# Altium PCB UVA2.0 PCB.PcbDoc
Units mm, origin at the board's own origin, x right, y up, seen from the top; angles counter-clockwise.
Board outline 98.11 x 98.11 mm, 2 copper layers (Top Layer, Bottom Layer); 74 components, 54 nets, 233 pads, 126 vias.
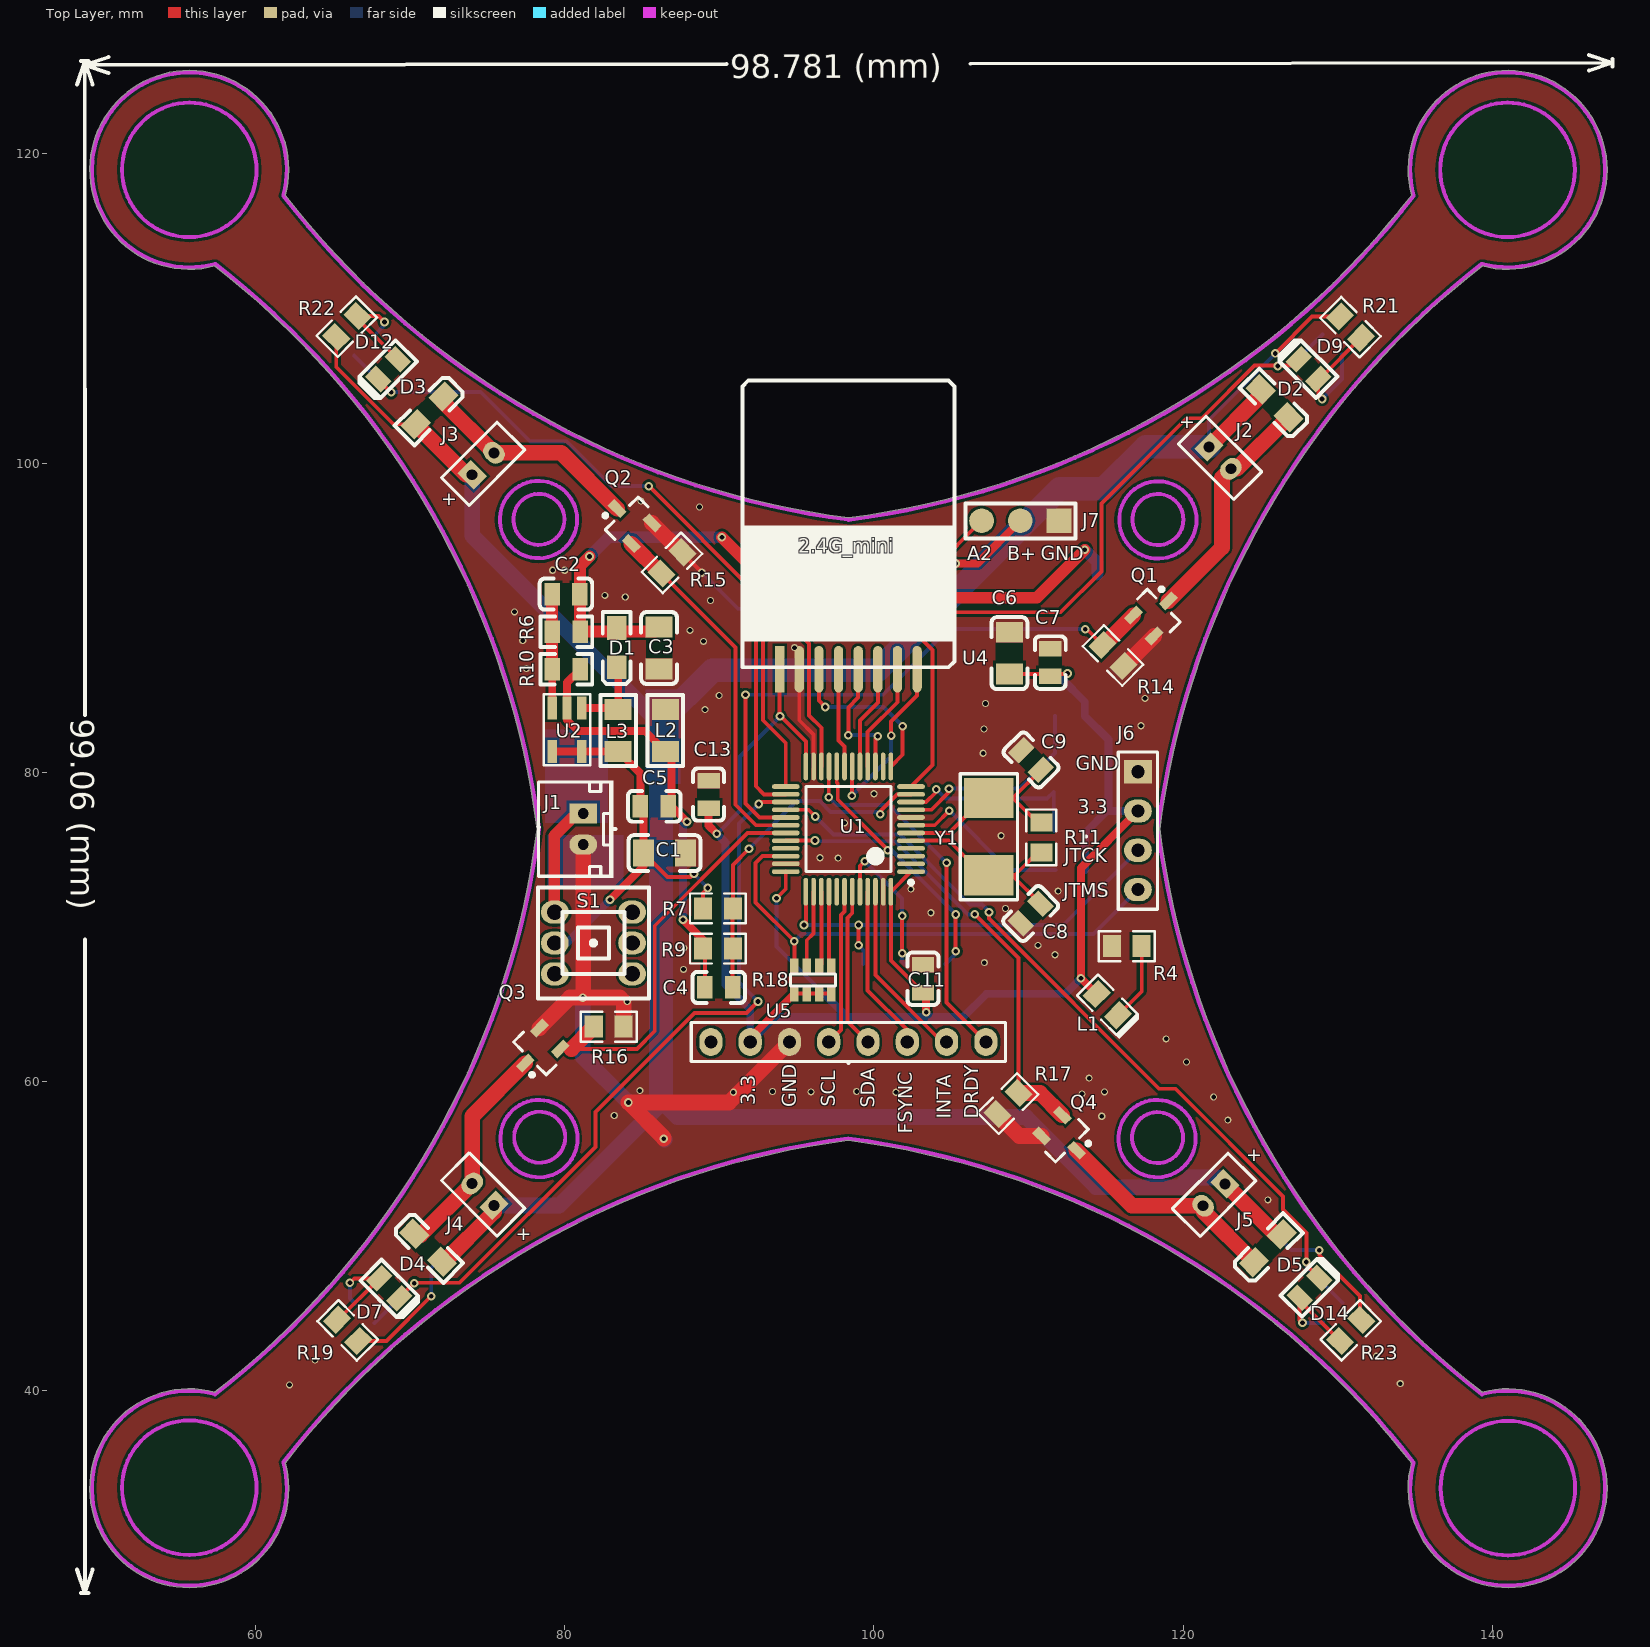
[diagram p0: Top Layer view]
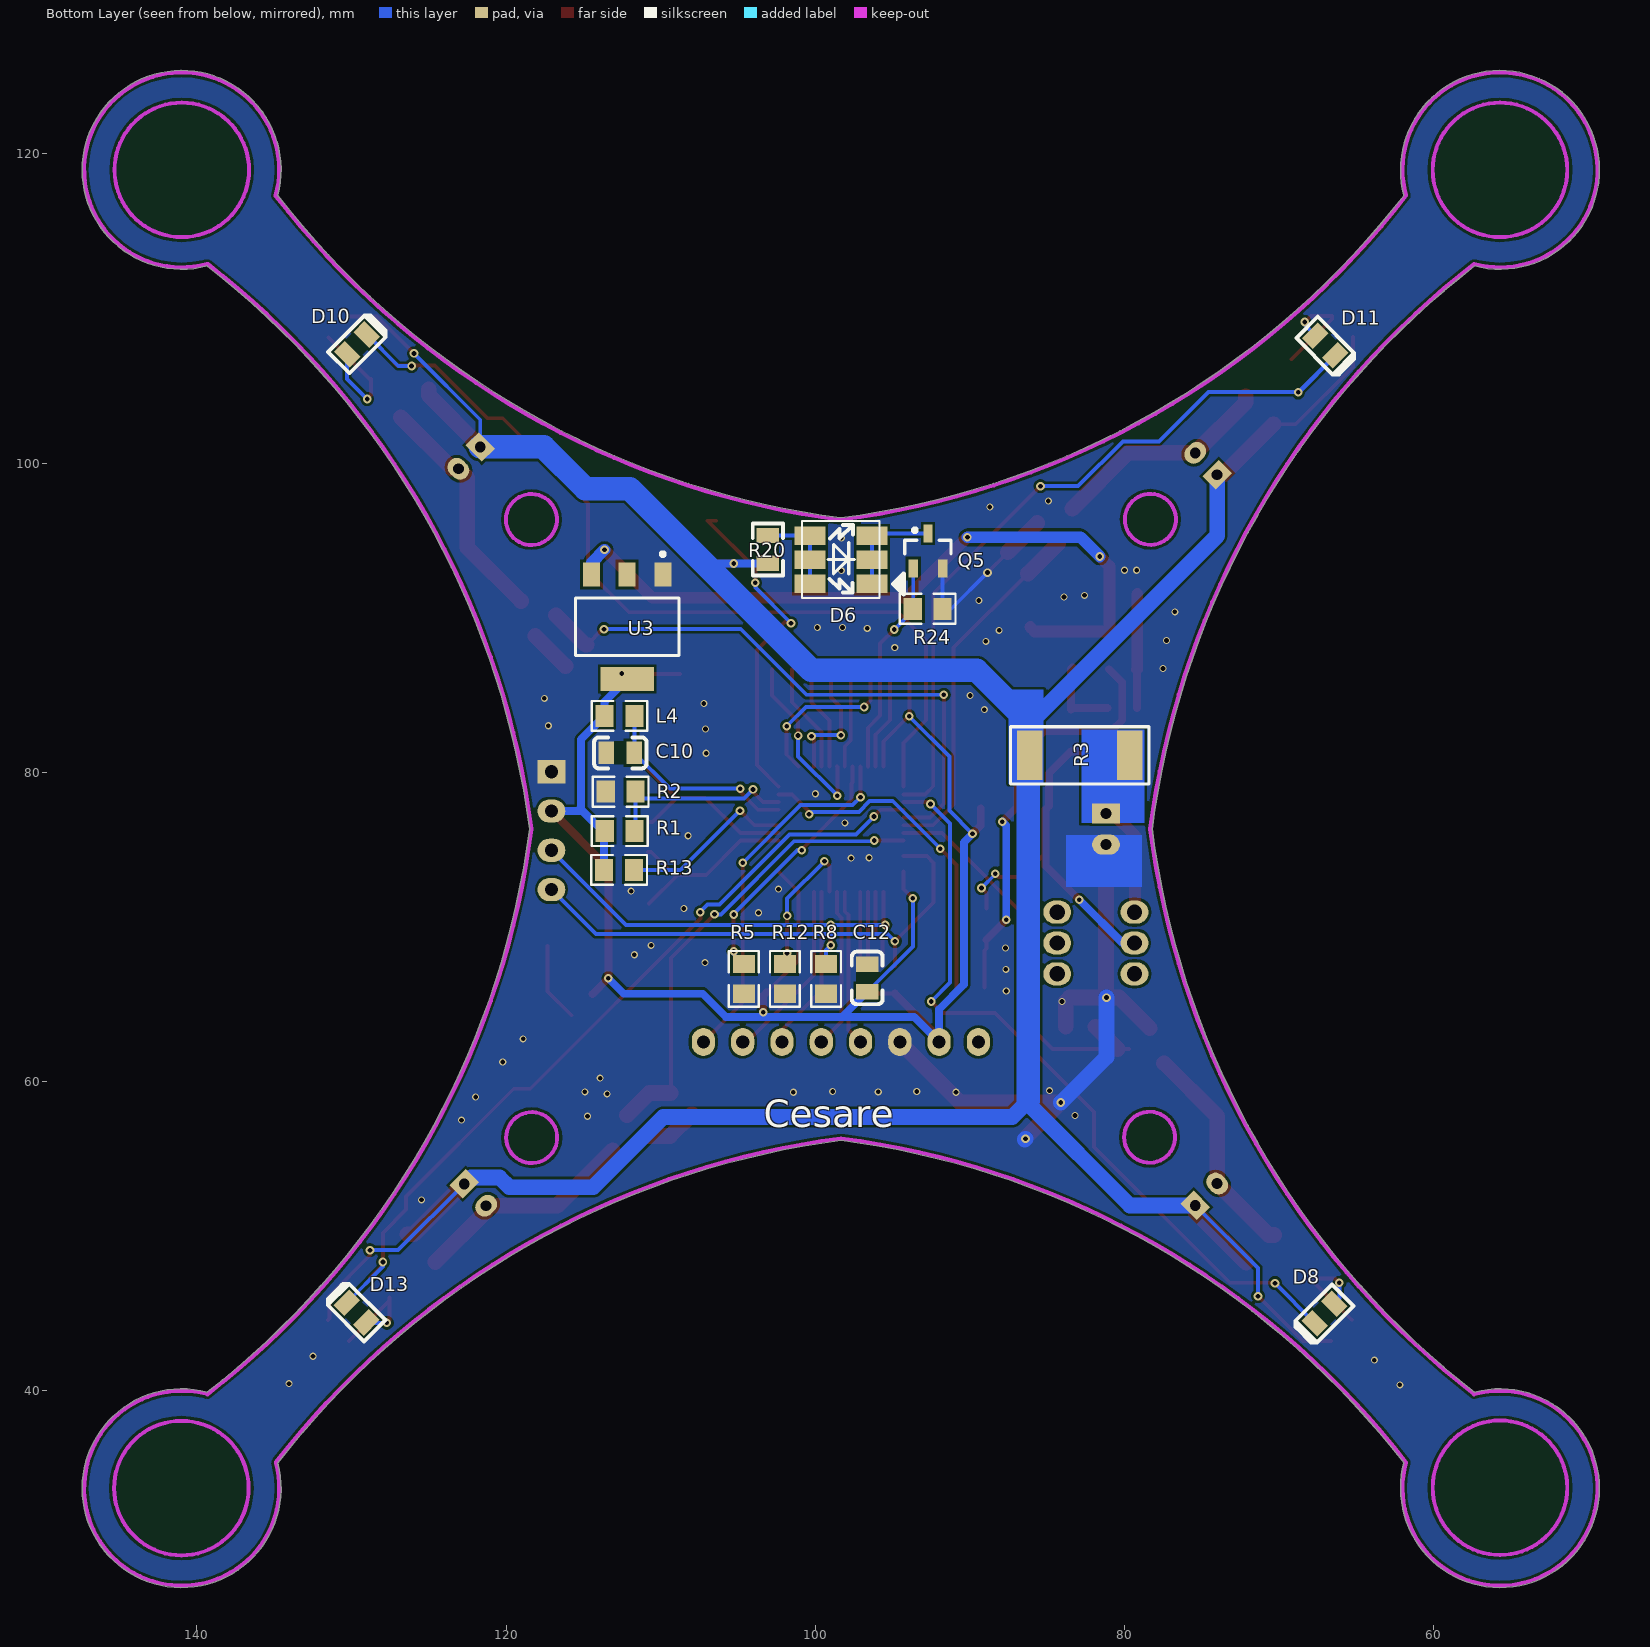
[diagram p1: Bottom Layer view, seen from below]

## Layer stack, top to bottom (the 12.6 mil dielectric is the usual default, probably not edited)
Top Solder: solder mask 0.0102, Solder Resist, Dk 3.5
Top Layer: signal copper 0.0356
Dielectric 1: dielectric 0.32, FR-4, Dk 4.8
Bottom Layer: signal copper 0.0356
Bottom Solder: solder mask 0.0102, Solder Resist, Dk 3.5

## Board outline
62.157,33.703 ccw(c55.73,33.703) 61.943,35.348 cw(c105.439,1.613) 98.338,56.198 cw(c91.255,1.611) 134.762,35.33 ccw(c140.981,33.703) 147.408,33.703 ccw(c140.981,33.703) 139.336,39.917 cw(c173.071,83.412) 118.484,76.329 cw(c173.071,69.245) 139.336,112.741 ccw(c140.981,118.954) 147.408,118.954 ccw(c140.981,118.954) 134.767,117.309 cw(c91.272,151.045) 98.355,96.457 cw(c105.439,151.045) 61.943,117.309 ccw(c55.73,118.954) 62.157,118.954 ccw(c55.73,118.954) 57.375,112.741 cw(c23.639,69.245) 78.226,76.329 cw(c23.639,83.412) 57.375,39.917 ccw(c55.73,33.703)

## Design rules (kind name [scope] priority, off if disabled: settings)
Clearance [All] p1: gap=0.178
PlaneConnect [All] p1: planeconnectstyle=Direct reliefexpansion=0.508 reliefentries=4 reliefconductorwidth=0.254 reliefairgap=0.254
PolygonConnect [All] p1: connectstyle=Direct reliefconductorwidth=0.254 reliefentries=4 polygonreliefangle="90 Angle" airgapwidth=0.254
RoutingVias [All] p1: holewidth=0.305 width=0.559 viastyle="Through Hole" minholewidth=0.305 minwidth=0.559 maxholewidth=0.711 maxwidth=1.27
SolderMaskExpansion [All] p1: expansion=0.102
Width [All] p1: maxlimit=1.524 minlimit=0.254 preferedwidth=0.254
28 further rules are at their usual default settings.

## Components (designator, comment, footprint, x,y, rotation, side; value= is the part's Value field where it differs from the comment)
C1 "10UF" 1206C 86.462,74.778 r180 top
C2 "3.3pF" 0805C 80.086,91.523 r180 top
C3 "4.7UF" 1206C 86.106,88.036 r270 top
C4 "100NF" 0805C 89.967,66.091 r180 top
C5 "4.7UF" 0805C 85.801,77.8 r0 top
C6 "10UF" 1206C 108.763,87.706 r90 top
C7 "0.1UF" 0805C 111.404,87.097 r90 top
C8 "20PF" 0805C 110.134,70.866 r45 top
C9 "20PF" 0805C 110.16,80.797 r315 top
C10 "100NF" 0805C 112.614,81.255 r0 bottom
C11 "100NF" 0805C 103.175,66.65 r90 top
C12 "100NF" 0805C 96.647,66.7 r90 bottom
C13 "100NF" 0805C 89.306,78.562 r90 top
D1 "DIODE-S" C_SMA_3216 83.363,88.062 r90 top
D2 "DIODE-S" C_SMA_3216 125.908,103.861 r135 top
D3 "DIODE-S" C_SMA_3216 71.272,103.403 r225 top
D4 "DIODE-S" C_SMA_3216 71.171,49.251 r315 top
D5 "DIODE-S" C_SMA_3216 125.476,49.225 r45 top
D6 "LED" LED5050_RGB 98.349,93.751 r180 bottom
D7 "LED" 0805D 68.656,46.634 r315 top
D8 "LED" 0805D 67.081,45.009 r315 bottom
D9 "LED" 0805D 128.097,106.07 r135 top
D10 "LED" 0805D 129.642,107.671 r135 bottom
D11 "LED" 0805D 67.031,107.594 r225 bottom
D12 "LED" 0805D 68.58,106.07 r225 top
D13 "LED" 0805D 129.667,45.06 r45 bottom
D14 "LED" 0805D 128.168,46.66 r45 top
J1 "Li Battery - 3.7V" P2_2.0-2 81.204,76.327 r270 top locked
J2 "M1" P2_2.0-1 122.377,100.33 r135 top
J3 "M1" P2_2.0-1 74.727,99.949 r225 top
J4 "M1" P2_2.0-1 74.727,52.7 r315 top
J5 "M1" P2_2.0-1 121.996,52.68 r45 top
J6 "ST_LINK" P4_2.54-1 117.069,76.225 r270 top
J7 "SIP3" PC_3 111.963,96.266 r180 top
L1 "白" D0805 114.427,65.634 r315 top
L2 "10UH" 1206 86.512,82.702 r270 top
L3 "10UH" 1206 83.464,82.702 r270 top
L4 "INDUCTOR" R0805 112.674,83.642 r180 bottom
Q1 "SI2302" SI2302 118.237,90.297 r45 top
Q2 "SI2302" SI2302 84.176,96.241 r135 top
Q3 "SI2302" SI2302 78.257,61.976 r225 top
Q4 "SI2302" SI2302 112.319,56.363 r315 top
Q5 "SI2302" SI2302 92.735,94.31 r90 bottom
R1 "RES" R0805 112.649,76.2 r0 bottom
R2 "RES" R0805 112.598,78.74 r180 bottom
R3 "0R" "2512R - duplicate" 82.906,81.102 r0 bottom
R4 "Res1" R0805 116.357,68.758 r180 top
R5 "RES" R0805 104.633,66.65 r270 bottom
R6 "620K" 0805R 80.108,89.083 r0 top
R7 "RES" R0805 89.907,71.196 r0 top
R8 "RES" R0805 99.314,66.65 r270 bottom
R9 "RES" R0805 89.918,68.604 r180 top
R10 "200K" 0805R 80.108,86.665 r180 top
R11 "RES" R0805 110.82,75.794 r270 top
R12 "RES" R0805 101.97,66.639 r90 bottom
R13 "RES" R0805 112.7,73.685 r180 bottom
R14 "RES" R0805 115.468,87.554 r135 top
R15 "RES" R0805 86.944,93.548 r225 top
R16 "RES" R0805 82.855,63.551 r180 top
R17 "RES" R0805 108.661,58.572 r45 top
R18 "10k" 8P4R_0603 96.037,66.573 r90 top
R19 "RES" R0805 65.964,43.917 r315 top
R20 "100R" 0805R 103.073,94.412 r90 bottom
R21 "RES" R0805 130.81,108.788 r315 top
R22 "RES" R0805 65.913,108.814 r45 top
R23 "RES" R0805 130.835,43.917 r225 top
R24 "RES" R0805 92.735,90.576 r0 bottom
S1 "SW-DPDT" KEY_KFT7.0 81.864,68.961 r180 top locked
U1 "STM32F103C8T6" LQFP48_N 98.349,76.327 r180 top locked
U2 "TPS6140" SOT-23-5 81.102,84.15 r270 top
U3 "AMS1117" ZZ311 112.166,89.408 r0 bottom
U4 "2.4G" 2.4G_mini 93.904,86.665 r0 top locked
U5 "GY_86" P8_2.54-1 98.349,62.56 r0 top locked
Y1 "CRYSTAL1" Y2 107.417,75.844 r270 top

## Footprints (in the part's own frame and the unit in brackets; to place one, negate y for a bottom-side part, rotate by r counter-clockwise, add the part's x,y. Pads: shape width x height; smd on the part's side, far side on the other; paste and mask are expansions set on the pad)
2.4G_mini [mm]
  rect 0.6x3 smd: 1(0,0)
  oval 0.6x3 smd: 2(1.27,0) 3(2.54,0) 4(3.81,0) 5(5.08,0) 6(6.35,0) 7(7.62,0) 8(8.89,0)
  silkscreen extent -2.41,0.13 11.3,18.67
8P4R_0603 [mil]
  rect 40x21.65 smd: 1(-35,46.5) 2(35,46.5) 3(-35,15) 4(35,15) 5(-35,-16.5) 6(35,-16.5) 7(-35,-47.99) 8(35,-47.99)
  silkscreen extent -15,-59 15,56
0805C [mm]
  rect 1x1.45 smd: 1(-0.9,0) 2(0.9,0)
  Top Layer pour cut-out: -0.432,0.749 -0.432,-0.737 0.406,-0.737 0.406,0.749
  silkscreen extent -1.7,-1 1.7,1, body extent -1,-0.61 1,0.64, height 1
0805D [mm]
  rect 1x1.45 smd: 1(-0.9,0) 2(0.9,0)
  Top Layer pour cut-out: -0.432,0.749 -0.432,-0.737 0.406,-0.737 0.406,0.749
  silkscreen extent -1.66,-0.98 1.94,0.98, body extent -1.16,-0.68 1.14,0.67, height 0.76
0805R [mm]
  rect 1x1.45 smd: 1(-0.9,0) 2(0.9,0)
  Top Layer pour cut-out: -0.432,0.749 -0.432,-0.737 0.406,-0.737 0.406,0.749
  silkscreen extent -1.68,-0.98 1.68,0.98, body extent -1,-0.62 1,0.63, height 0.5
1206 [mm]
  rect 1.35x1.75 smd: 1(-1.35,0) 2(1.35,0)
  Top Layer pour cut-out: -0.686,0.864 0.673,0.864 0.673,-0.876 -0.686,-0.876
  silkscreen extent -2.3,-1.14 2.3,1.14, body extent -1.61,-0.81 1.59,0.79, height 1.5
1206C [mm]
  rect 1.35x1.75 smd: 1(-1.35,0) 2(1.35,0)
  Top Layer pour cut-out: -0.686,0.876 0.673,0.876 0.673,-0.864 -0.686,-0.864
  silkscreen extent -2.32,-1.16 2.32,1.16, body extent -1.65,-0.81 1.55,0.79, height 1
"2512R - duplicate" [mm]
  rect 1.65x3.2 smd: 1(-3.24,0) 2(3.24,0)
  silkscreen extent -4.49,-1.84 4.48,1.87, body extent -2.48,-1.26 2.52,1.24, height 0.6
C_SMA_3216 [mil] "英制1206/公制3216"
  rect 60x50 smd: 1(-50,0) 2(50,0)
  Top Layer pour cut-out: -19.68,29.53 19.68,29.53 19.68,-29.53 -19.68,-29.53
  silkscreen extent -93,-35 91,35, body extent -66,-33 68,33, height 67
D0805 [mil]
  rect 46x56 smd: 1(-1,0) 2(75,0)
  silkscreen extent -34,-40 120,40
KEY_KFT7.0 [mm] "7X7mm"
  oval 1.8x1.5 hole 1: 1(-2.5,2) 2(-2.5,0) 3(-2.5,-2) 4(2.5,-2) 5(2.5,0) 6(2.5,2)
  silkscreen extent -3.6,-3.6 3.6,3.6
LED5050_RGB [mm]
  rect 2x1.2 smd paste-0.05 mask+0.05: 1(-2,1.55) 2(-2,0) 3(-2,-1.55) 4(2,-1.55) 5(2,0) 6(2,1.55)
  silkscreen extent -2.51,-2.49 4.06,2.51, body extent -2.68,-2.5 2.62,2.5, height 1.6
LQFP48_N [mm]
  oval 1.8x0.3 smd: 1(-4.05,2.75) 2(-4.05,2.25) 3(-4.05,1.75) 4(-4.05,1.25) 5(-4.05,0.75) 6(-4.05,0.25) 7(-4.05,-0.25) 8(-4.05,-0.75) 9(-4.05,-1.25) 10(-4.05,-1.75) 11(-4.05,-2.25) 12(-4.05,-2.75) 25(4.05,-2.75) 26(4.05,-2.25) 27(4.05,-1.75) 28(4.05,-1.25) 29(4.05,-0.75) 30(4.05,-0.25) 31(4.05,0.25) 32(4.05,0.75) 33(4.05,1.25) 34(4.05,1.75) 35(4.05,2.25) 36(4.05,2.75)
  oval 0.3x1.8 smd: 13(-2.75,-4.05) 14(-2.25,-4.05) 15(-1.75,-4.05) 16(-1.25,-4.05) 17(-0.75,-4.05) 18(-0.25,-4.05) 19(0.25,-4.05) 20(0.75,-4.05) 21(1.25,-4.05) 22(1.75,-4.05) 23(2.25,-4.05) 24(2.75,-4.05) 37(2.75,4.05) 38(2.25,4.05) 39(1.75,4.05) 40(1.25,4.05) 41(0.75,4.05) 42(0.25,4.05) 43(-0.25,4.05) 44(-0.75,4.05) 45(-1.25,4.05) 46(-1.75,4.05) 47(-2.25,4.05) 48(-2.75,4.05)
  silkscreen extent -4.18,-2.75 2.75,3.57
P2_2.0-1 [mm]
  rect 1.2x1.5 hole 0.7: 1(1,0)
  oval 1.2x1.5 hole 0.7: 2(-1,0)
  silkscreen extent -2.54,-1.27 2.54,1.27
P2_2.0-2 [mm]
  rect 1.3x1.8 hole 0.7: 1(-1,0)
  oval 1.3x1.8 hole 0.7: 2(1,0)
  silkscreen extent -3.15,-2.9 3.16,1.97, body extent -2.99,-2.8 3.01,1.7, height 6
P4_2.54-1 [mm]
  rect 1.5x1.8 hole 0.85: 1(-3.81,0)
  oval 1.5x1.8 hole 0.85: 2(-1.27,0) 3(1.27,0) 4(3.81,0)
  silkscreen extent -5.08,-1.27 5.08,1.27, body extent -5.08,-1.47 5.08,1.45, height 8.56
P8_2.54-1 [mm]
  oval 1.5x1.8 hole 0.85: 1(-8.89,0) 2(-6.35,0) 3(-3.81,0) 4(-1.27,0) 5(1.27,0) 6(3.81,0) 7(6.35,0) 8(8.89,0)
  silkscreen extent -10.16,-1.27 10.16,1.27, body extent -10.16,-1.47 10.16,1.45, height 8.56
PC_3 [mm]
  rect 1.6x1.6 smd: 1(0,0)
  round 1.6 smd: 2(2.5,0) 3(5,0)
  silkscreen extent -1.07,-1.12 6.05,1.14
R0805 [mil]
  rect 46x56 smd: 1(-37.79,0.07) 2(38.21,0.07)
  silkscreen extent -71,-38 71,38
SI2302 [mm]
  rect 1.15x0.6 smd: 1(-1.128,0.934) 2(-1.128,-0.966) 3(1.122,-0.016)
  silkscreen extent -0.2,-1.52 1.47,1.48, body extent -0.7,-1.52 0.7,1.48, height 1.1
SOT-23-5 [mm]
  rect 1.5x0.6 smd: 1(0,0) 2(0,-0.95) 3(0,-1.9) 4(2.8,-1.9) 5(2.8,0)
  silkscreen extent -0.9,-2.45 3.7,0.55
Y2 [mm]
  rect 2.6x3.2 smd: 1(-2.5,0) 2(2.5,0)
  silkscreen extent -4.06,-1.83 4.09,1.87
ZZ311 [mm]
  rect 1.1x1.55 smd: 1(-2.3,-3.375) 2(0,-3.375) 3(2.3,-3.375)
  rect 3.45x1.55 smd: 4(0,3.375)
  silkscreen extent -3.35,-4.82 3.35,1.85

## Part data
C1 C2 C3 C4 C5 C6 C7 C8 C9 C10 C11 C12 C13: library part CAP, "Capacitor/小容量电容"
D1 D2 D3 D4 D5: "SCHOTTKEY"
D6: library part LED_5050RGB
J1 J2 J3 J4 J5: library part SIP2
J6: library part SIP4
L1: library part LED
L2 L3: library part L
R1 R2 R5 R7 R8 R9 R11 R12 R13 R14 R15 R16 R17 R19 R21 R22 R23 R24: "Semiconductor Resistor"
R3: library part Res_1
R4: "Resistor"
R6 R10 R20: library part Res
R18: library part 8P4R_0603, "8P4R_0603"
S1: "Double-Pole, Double-Throw Switch"
U1: "STM32 ARM-based 32-bit MCU with 64 Kbytes Flash, 48-pin LQFP, Industrial Temperature"
U3: "Header, 2-Pin"
U4: library part 2.4G_mini

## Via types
v1: diameter 0.559, hole 0.305, Top Layer to Bottom Layer, 65 vias
v2: diameter 0.457, hole 0.305, Top Layer to Bottom Layer, 61 vias

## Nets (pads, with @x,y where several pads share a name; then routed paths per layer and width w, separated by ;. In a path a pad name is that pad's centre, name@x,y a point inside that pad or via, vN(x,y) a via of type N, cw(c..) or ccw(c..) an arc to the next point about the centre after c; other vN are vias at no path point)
2.4_CE: U1.13 U4.3 | length 11
  Top Layer w0.254: U4.3 96.444,84.633 v1(96.85,84.226) ; U1.13 101.854,81.132 v1(101.854,82.982)
  Bottom Layer w0.254: v1(96.85,84.226) 100.609,84.226 v1(101.854,82.982)
2.4_CSN: U1.19 U4.4 | length 6.4
  Top Layer w0.254: U4.4 97.714,82.042 98.099,81.657 U1.19
2.4_IRQ: U1.18 U4.8 | length 11.8
  Top Layer w0.254: v1(98.577,78.486) 98.577,80.356 U1.18 ; v1(101.117,82.372) 101.117,83.287 102.794,84.963 U4.8
  Bottom Layer w0.254: v1(98.577,78.486) 101.117,81.026 v1(101.117,82.372)
2.4_MISO: U1.16 U4.7 | length 7.1
  Top Layer w0.254: U1.16 99.599,82.606 101.524,84.531 U4.7
2.4_MOSI: U1.17 U4.6 | length 6.8
  Top Layer w0.254: U1.17 99.099,83.351 100.254,84.506 U4.6
2.4_SCK: U1.15 U4.5 | length 8.5
  Top Layer w0.254: v1(98.349,82.398) 98.349,84.201 98.984,84.836 U4.5 ; U1.15 100.099,82.166 v1(100.254,82.321)
  Bottom Layer w0.254: v1(98.349,82.398) 100.178,82.398 v1(100.254,82.321)
505LED: Q5.1 R24.2 U1.22 | length 14
  Top Layer w0.254: v1(94.894,89.23) 95.809,88.316 95.809,83.668 96.599,82.878 U1.22
  Bottom Layer w0.254: Q5.1 93.669,90.455 v1(94.894,89.23)
+3.3V: C6.1 C7.1 C11.1 C12.1 C13.1 J6.2 L1.1 L4.1 R1.2 R13.1 R18.1 R18.3 R18.5 R18.7 U1.1 U1.24 U1.36 U1.48 U3.4 U4.1 U5.2 | length 119.1
  Top Layer w0.254: v1(93.701,71.857) 94.299,72.455 U1.36 ; U4.1 93.904,83.693 v1@93.929,83.668 ; v1(93.929,83.617) v1@93.929,83.668 ; R18.1 R18.3 R18.5 R18.7 ; U1.24 95.599,81.998 v1@93.929,83.668 ; U1.1 U1.48 101.099,67.826 C11.1 ; C6.1 112.49,86.356 v1(112.519,86.385)
  Top Layer w0.508: C13.1 89.306,76.556 v1(89.84,76.022) ; U5.2 91.999,62.827 R18.1 ; C11.1 103.378,65.546 v1(103.378,64.491) ; L1.1 v1(113.386,66.675) 113.386,73.812 J6.2
  Bottom Layer w0.254: v1(89.84,76.022) 91.338,77.521 91.338,81.026 v1(93.929,83.617) ; v1(93.701,71.857) 93.701,68.747 C12.1 ; U3.4 v1(112.519,86.385)
  Bottom Layer w0.508: v1(89.84,76.022) 90.399,75.463 90.399,66.279 91.999,64.679 U5.2 93.624,64.186 98.262,64.186 ; C12.1 98.262,64.186 ; 103.378,64.186 98.262,64.186 ; v1(103.378,64.491) 103.403,64.465 103.403,64.186 105.798,64.186 107.291,65.679 112.39,65.679 v1(113.386,66.675) ; U3.4 113.634,84.565 L4.1 115.164,82.115 115.164,77.699 115.367,77.495 ; R13.1 113.66,76.093 115.062,77.495 J6.2
+5.0V: C2.1 C3.1 D1.2 R6.2 U3.3 | length 47.7
  Top Layer w0.762: v1(81.61,93.955) 80.986,93.331 C2.1 80.986,89.104 85.824,89.104 C3.1 ; v1(90.17,95.199) 94.082,91.288 110.541,91.288 v1(113.64,94.386)
  Bottom Layer w0.762: v1(81.61,93.955) 82.855,95.199 v1(90.17,95.199) ; v1(113.64,94.386) 114.466,93.56 U3.3
ADC: C4.1 R7.2 R9.1 U1.11 | length 22.1
  Top Layer w0.254: C4.1 90.867,71.187 R7.2 90.877,74.012 v1(91.923,75.057) ; v1(100.406,77.292) 100.406,77.478 101.506,78.577 U1.11
  Bottom Layer w0.254: v1(91.923,75.057) 94.996,78.13 96.507,78.13 97.192,77.445 100.254,77.445 v1(100.406,77.292)
BAT: J1.1 R3.1 S1.4 | length 7.4
  Top Layer w0.762: S1.4@79.35,70.942 79.324,70.968 79.324,75.895 80.756,77.327 J1.1
BAT+: D2.2 D3.2 D4.2 D5.2 J2.1 J3.1 J4.1 J5.1 J7.2 R3.2 R19.2 R20.1 R21.1 R22.1 R23.1 | length 216.8
  Top Layer w0.254: R22.1 65.233,106.217 68.945,102.505 D3.2 ; R19.2 68.479,43.232 v1(71.374,46.126) ; v1(125.959,107.086) 128.34,109.468 R21.1 ; v1(128.803,49.098) 128.803,48.768 131.432,46.139 131.432,44.677 R23.1
  Top Layer w0.508: v1(105.283,93.497) 106.695,93.497 J7.2
  Top Layer w1.016: D3.2 73.638,99.242 J3.1 ; D4.2@72.145,48.276 75.434,51.565 J4.1 ; J2.1 125.01,104.377 D2.2 ; J5.1 125.967,50.123 D5.2
  Bottom Layer w0.254: v1(71.374,46.126) 71.374,47.933 J4.1 ; J2.1 121.67,102.798 v1(125.959,107.086) ; J5.1 126.992,49.098 v1(128.803,49.098)
  Bottom Layer w0.508: R20.1 v1@105.283,93.512 ; v1(105.283,93.497) 106.858,93.497 107.01,93.345
  Bottom Layer w1.016: J3.1 74.02,95.297 86.144,83.172 ; J4.1 79.654,51.993 86.233,58.572 ; 86.233,58.75 87.274,57.709 109.83,57.709 114.364,53.175 119.799,53.175 120.421,53.797 122.293,53.797 J5.1
  Bottom Layer w1.524: 86.144,83.172 89.56,86.589 100.254,86.589 107.01,93.345 112.014,98.349 114.884,98.349 117.573,101.037 J2.1 ; 86.233,58.75 86.233,80.05 R3.2@86.716,80.532
GND: C1.1 C3.2 C6.2 C7.2 C8.1 C9.1 C10.2 C11.2 C12.2 C13.2 J1.2 J6.1 J7.1 L2.1 Q1.2 Q2.2 Q3.2 Q4.2 Q5.2 R2.1 R4.2 R5.2 R8.2 R12.1 R14.1 R15.1 R16.1 R17.1 R24.1 U1.8 U1.23 U1.35 U1.47 U3.1 U4.2 U5.3 | length 65.2
  Top Layer w0.254: R15.1@87.557,94.226 87.562,94.226 v1(88.875,92.913) ; U4.2 95.174,83.363 96.099,82.438 U1.23
  Top Layer w1.016: Q3.2 80.346,65.43 v1(81.178,65.43) ; J1.2 81.204,65.456 v1(81.178,65.43) ; R16.1 83.815,65.182 83.566,65.43 v1(81.178,65.43) ; Q2.2 R15.1@87.557,94.226 ; v1(86.411,56.312) 86.411,56.363 v1(84.125,58.649) 90.627,58.649 U5.3 ; R17.1 109.399,56.477 Q4.2 ; R14.1 116.18,86.874 Q1.2
  Bottom Layer w0.254: v1(88.875,92.913) 91.213,90.575 R24.1 91.769,90.581 Q5.2
  Bottom Layer w1.016: v1(81.178,65.43) 81.178,61.595 v1(84.125,58.649) ; v1(86.411,56.312) v1@86.462,56.261
  other v2: 62.205,40.386 134.036,40.462 63.856,41.986 132.486,42.24 125.476,52.349 122.885,57.506 114.732,57.76 83.21,57.81 121.971,59.004 113.462,59.207 90.907,59.309 101.422,59.309 95.936,59.334 114.91,59.334 93.447,59.36 98.882,59.36 84.861,59.411 113.919,60.223 120.218,61.265 118.897,62.763 84.049,65.176 87.655,65.862 87.681,67.259 107.137,67.691 111.709,68.199 87.706,68.631 110.617,68.809 103.683,70.917 108.509,71.196 111.912,72.314 102.387,72.441 97.688,74.447 96.52,74.473 108.229,75.895 98.095,76.733 100,78.613 107.061,81.229 107.112,82.804 117.272,83.007 89.078,84.049 107.213,84.455 117.526,84.785 89.992,84.963 77.521,86.716 94.869,88.062 88.976,88.468 77.292,88.519 88.113,89.179 96.647,89.306 98.247,89.357 99.873,89.357 76.759,90.373 89.433,91.11 83.922,91.338 82.601,91.44 98.323,93.04 79.223,93.066 80.01,93.066 98.323,95.148 88.722,97.155 84.938,97.536
GY_DRDY: U1.21 U5.8 | length 24
  Top Layer w0.254: v1(97.079,78.384) 97.079,80.357 U1.21 ; v1(104.699,74.143) 104.699,65.1 U5.8
  Bottom Layer w0.254: v1(97.079,78.384) 97.587,77.876 100.965,77.876 v1(104.699,74.143)
GY_FSYNC: U1.45 U5.6 | length 10.8
  Top Layer w0.254: U1.45 99.599,65.882 102.159,63.322 U5.6
GY_INTA: U1.46 U5.7 | length 11.8
  Top Layer w0.254: U1.46 100.099,66.881 104.419,62.56 U5.7
GY_SCL: U1.42 U5.4 | length 10.1
  Top Layer w0.254: U5.4 97.866,63.348 97.866,70.765 98.099,70.998 U1.42
GY_SDA: U1.43 U5.5 | length 10.4
  Top Layer w0.254: U1.43 98.599,70.887 98.298,70.587 98.298,63.881 U5.5
JTCK: J6.3 R8.1 U1.37 | length 28.4
  Top Layer w0.254: v1(95.479,70.129) 95.599,70.25 U1.37 ; v1(99.009,68.809) v1(99.009,70.129)
  Bottom Layer w0.254: v1(95.479,70.129) v1(99.009,70.129) 112.243,70.129 J6.3 ; v1(99.009,68.809) 99.312,68.506 R8.1
JTDI: R18.4 U1.38 | length 5
  Top Layer w0.254: R18.4 95.656,69.139 96.099,69.581 U1.38
JTDO: R18.6 U1.39 | length 4.9
  Top Layer w0.254: R18.6 96.599,67.605 U1.39
JTMS: J6.4 R18.2 U1.34 | length 33.4
  Top Layer w0.254: U1.34 92.789,74.577 92.354,74.143 92.354,71.577 v1(94.856,69.075) R18.2
  Bottom Layer w0.254: v1(94.856,69.075) 95.326,69.545 114.198,69.545 J6.4
JTRST: R18.8 U1.40 | length 4.9
  Top Layer w0.254: U1.40 97.099,67.62 R18.8
LED_1: D9.2 D10.2 U1.25 | length 58.5
  Top Layer w0.254: U1.25 94.299,81.901 92.837,83.363 92.837,88.519 94.666,90.348 112.065,90.348 114.706,92.989 114.706,97.384 120.218,102.895 121.209,102.895 124.612,106.299 127.053,106.299 D9.2
  Bottom Layer w0.254: v1(126.111,106.274) 126.972,106.274 D10.2
LED_2: D11.2 D12.2 U1.26 | length 51.6
  Top Layer w0.254: D12.2 67.944,105.409 v1(68.783,104.569) ; v1(85.446,98.501) 92.38,91.567 92.38,79.096 92.898,78.577 U1.26
  Bottom Layer w0.254: v1(68.783,104.569) D11.2 66.394,106.91 68.707,104.597 74.574,104.597 77.775,101.397 80.112,101.397 83.007,98.501 v1(85.446,98.501)
LED_3: D7.2 D8.2 U1.27 | length 51.7
  Top Layer w0.254: D7.2 v1@70.27,46.976 ; v1@70.285,46.99 73.198,46.99 81.991,55.783 81.991,58.039 88.392,64.44 91.77,64.44 v1(92.507,65.176) ; v1(92.558,77.953) 92.682,78.077 U1.27
  Bottom Layer w0.254: D8.2 67.718,44.401 v1(70.282,46.965) ; v1(92.507,65.176) 91.288,66.396 91.288,76.683 v1(92.558,77.953)
LED_4: D13.2 D14.2 U1.28 | length 52.6
  Top Layer w0.254: U1.28 95.778,77.577 v1(96.215,77.14) ; v1(107.442,70.942) 107.442,70.536 118.44,59.538 119.507,59.538 126.467,52.578 126.467,51.714 127.965,50.216 v1(127.965,48.336) 127.965,48.136 D14.2
  Bottom Layer w0.254: v1(96.215,77.14) 97.384,75.971 101.676,75.971 106.197,71.45 106.985,71.45 107.442,70.993 v1(107.442,70.942) ; v1(127.965,48.336) 127.965,48.034 D13.2
MOS_1: Q1.1 R14.2 U1.29 | length 38.1
  Top Layer w0.254: v1(91.694,85.014) 91.694,77.978 92.595,77.077 U1.29 ; v1(113.665,89.256) 113.764,89.256 R14.2
  Top Layer w1.016: R14.2 114.858,88.239 Q1.1
  Bottom Layer w0.254: v1(91.694,85.014) 100.584,85.014 104.826,89.256 v1(113.665,89.256)
MOS_2: Q2.1 R15.2 U1.30 | length 23.5
  Top Layer w0.254: R15.2 91.059,88.061 91.059,77.902 92.384,76.577 U1.30
  Top Layer w1.016: Q2.1 86.235,92.861 R15.2
MOS_3: Q3.1 R16.2 U1.31 | length 26.4
  Top Layer w0.254: Q3.1 80.448,62.113 84.668,62.113 85.827,63.271 85.827,70.079 91.825,76.077 U1.31
  Top Layer w1.016: 80.448,62.113 R16.2
MOS_4: Q4.1 R17.2 U1.32 | length 30.4
  Top Layer w0.254: U1.32 96.176,75.577 v1(96.19,75.59) ; v1(106.528,70.815) 109.346,67.997 R17.2
  Top Layer w1.016: R17.2 110.742,59.26 Q4.1
  Bottom Layer w0.254: v1(96.19,75.59) 96.241,75.54 101.371,75.54 106.096,70.815 v1(106.528,70.815)
NetC1_2: C1.2 C5.1 L3.2 R7.1 S1.5 U2.4 U2.5 | length 26.9
  Top Layer w0.254: C1.2 86.66,73.229 88.151,73.229 v1(88.367,73.445) ; R7.1 88.947,72.208 v1(89.256,72.517)
  Top Layer w0.508: U2.4 U2.5 83.462,81.35 L3.2 84.901,79.916 C5.1 85.112,77.59 C1.2 85.112,73.936 v1(82.931,71.755)
  Bottom Layer w0.254: v1(88.367,73.445) 88.367,73.406 v1(89.256,72.517)
  Bottom Layer w0.508: S1.5 80.137,68.961 v1(82.931,71.755)
NetC2_2: C2.2 R6.1 R10.2 U2.3 | length 7.4
  Top Layer w0.508: U2.3 79.202,86.659 R10.2
  Top Layer w0.762: C2.2 79.186,86.686 R10.2
NetC8_2: C8.2 R11.2 U1.5 Y1.2 | length 12.6
  Top Layer w0.254: U1.5 104.839,75.577 107.072,73.344 Y1.2 109.108,73.344 110.612,74.848 R11.2@110.822,74.848 ; Y1.2@108.929,73.344 C8.2
NetC9_2: C9.2 R11.1 U1.6 Y1.1 | length 12.6
  Top Layer w0.254: U1.6 104.855,76.077 107.123,78.344 Y1.1 Y1.1@108.98,78.344 ; C9.2 Y1.1@108.98,78.344 ; R11.1@110.822,76.779 110.545,76.779 Y1.1@108.98,78.344
NetC10_1: C10.1 L4.2 U1.9 | length 13.4
  Top Layer w0.254: U1.9 103.714,77.577 104.851,78.715 v1(104.851,78.943)
  Bottom Layer w0.254: v1(104.851,78.943) 109.403,78.943 C10.1 111.704,81.265 L4.2
NetD1_1: D1.1 L3.1 U2.1 | length 5.2
  Top Layer w0.508: U2.1 83.367,84.15 L3.1 83.464,86.69 D1.1
NetD2_1: D2.1 J2.2 Q1.3 | length 15.3
  Top Layer w1.016: Q1.3 122.504,94.542 122.504,99.043 J2.2 123.466,99.623 D2.1
NetD3_1: D3.1 J3.2 Q2.3 | length 14.5
  Top Layer w1.016: D3.1 72.17,103.92 J3.2 79.783,100.656 Q2.3
NetD4_1: D4.1 J4.2 Q3.3 | length 14.3
  Top Layer w1.016: D4.1@70.349,50.072 70.685,50.072 J4.2 74.02,57.761 Q3.3
NetD5_1: D5.1 J5.2 Q4.3 | length 14.7
  Top Layer w1.016: Q4.3 116.686,51.972 J5.2 121.289,51.616 D5.1
NetD6_1: D6.1 D6.2 D6.3 R20.2 | length 5.8
  Bottom Layer w0.254: D6.3 D6.1 100.359,95.312 R20.2
NetD6_4: D6.4 D6.5 D6.6 Q5.3 | length 6.8
  Bottom Layer w0.254: Q5.3 96.218,95.432 D6.6 D6.4
NetD7_1: D7.1 D8.1 R19.1 | length 7.3
  Top Layer w0.254: R19.1 65.346,44.597 D7.1 66.397,47.271 v1(66.116,46.99)
  Bottom Layer w0.254: v1(66.116,46.99) 66.116,45.974 D8.1
NetD9_1: D9.1 D10.1 R21.2 | length 8.7
  Top Layer w0.254: v1(128.981,104.14) 128.733,104.388 D9.1 128.828,105.434 R21.2
  Bottom Layer w0.254: v1(128.981,104.14) 130.278,105.437 D10.1
NetD11_1: D11.1 D12.1 R22.2 | length 7
  Top Layer w0.254: v1(68.351,109.118) 67.969,109.501 R22.2 66.598,109.325 D12.1
  Bottom Layer w0.254: D11.1 68.351,108.915 v1(68.351,109.118)
NetD13_1: D13.1 D14.1 R23.2 | length 6.7
  Top Layer w0.254: D14.1 D14.1@127.532,45.847 ; v1(127.711,44.399) 127.532,44.578 D14.1@127.532,45.847 ; R23.2 D14.1@127.532,45.847
  Bottom Layer w0.254: v1(127.711,44.399) 129.007,44.399 D13.1
NetL1_2: L1.2 R4.1 | length 5.1
  Top Layer w0.254: L1.2 117.317,65.83 R4.1
NetR1_1: R1.1 R2.2 U1.10 | length 12.6
  Top Layer w0.254: U1.10 103.375,78.077 104.038,78.74 v1(104.038,78.892)
  Bottom Layer w0.254: v1(104.038,78.892) 104.623,78.308 111.194,78.308 R2.2 111.628,76.26 R1.1
NetR5_1: R5.1 U1.20 | length 16.4
  Top Layer w0.254: U1.20 97.599,79.338 97.663,79.273 97.663,78.232 v1@100.914,74.981 ; v1(105.283,68.428) v1(105.283,70.802)
  Bottom Layer w0.254: v1(100.889,74.955) 100.914,74.981 101.143,74.981 105.283,70.841 v1(105.283,70.802) ; R5.1 105.283,68.261 v1(105.283,68.428)
NetR12_2: R12.2 U1.44 | length 9.8
  Top Layer w0.254: U1.44 99.099,73.927 v1(99.416,74.244) ; v1(101.829,68.301) v1(101.829,70.714)
  Bottom Layer w0.254: v1(99.416,74.244) 101.829,71.831 v1(101.829,70.714) ; v1(101.829,68.301) 101.829,67.753 R12.2
NetR13_2: R13.2 U1.7 | length 11.3
  Top Layer w0.254: U1.7 103.933,76.577 v1(104.877,77.521)
  Bottom Layer w0.254: v1(104.877,77.521) 108.71,73.687 R13.2
OUT_1: J7.3 U1.12 | length 21.8
  Top Layer w0.254: v1(101.578,89.637) 101.654,89.713 101.981,89.713 103.789,87.905 103.789,80.467 U1.12 ; v1(103.886,92.253) 103.886,93.189 J7.3 J7.3@106.426,96.266
  Bottom Layer w0.254: v1(101.578,89.637) 103.886,91.945 v1(103.886,92.253)
SGND: C4.2 C5.2 L2.2 R9.2 R10.1 U2.2 | length 27.4
  Top Layer w0.254: R9.2@88.947,69.168 R9.2 89.067,68.482 C4.2
  Top Layer w0.508: R10.1 80.152,85.809 U2.2 80.152,83.373 80.848,82.677 85.188,82.677 L2.2 86.919,80.946 86.919,77.8 v1(87.909,76.81) ; v1(87.655,70.46) R9.2@88.947,69.168
  Bottom Layer w0.508: v1(87.655,70.46) 87.655,76.556 v1(87.909,76.81)
pads on no net: S1.1 S1.2 S1.3 S1.6 U1.2 U1.3 U1.4 U1.14 U1.33 U1.41 U3.2 U5.1

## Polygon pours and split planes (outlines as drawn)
GND on Top Layer "Top Layer-No Net" (solid, remove dead copper, pour order 6): 33.442,140.589 36.947,137.084 171.567,137.084 171.567,27.864 158.308,14.605 156.657,12.954 31.969,12.954
GND on Bottom Layer "Top Layer-No Net" (solid, remove dead copper, pour order 8): 36.386,133.419 154.953,133.419 162.725,125.647 162.725,6.724 35.014,6.724 30.696,11.042

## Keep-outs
Top Layer:
  circle w0.254: c78.308,96.342 r2.5
  circle w0.254: c118.308,56.312 r2.5
  circle w0.254: c78.338,56.312 r2.5
  circle w0.254: c118.364,96.317 r2.5
Keep-Out Layer:
  circle w0.254: c55.73,33.737 r4.35
  circle w0.254: c140.998,33.712 r4.35
  circle w0.254: c140.972,118.954 r4.35
  circle w0.254: c118.343,56.375 r1.65
  circle w0.254: c78.389,56.401 r1.65
  circle w0.254: c118.364,96.342 r1.65
  circle w0.254: c78.338,96.355 r1.65
  circle w0.254: c55.73,118.954 r4.35
  lines w0.254: 57.36,39.789 ccw(c55.73,33.703) 61.804,35.376 cw(c105.439,1.613) 98.338,56.326 cw(c91.255,1.611) 134.89,35.374 ; 57.402,39.777 ccw(c23.639,83.412) 78.355,76.329 ccw(c23.639,69.245) 57.402,112.88 cw(c55.73,118.954) 61.815,117.324 ; 61.804,117.281 ccw(c105.439,151.045) 98.355,96.329 ; 98.349,96.317 ccw(c91.265,151.032) 134.9,117.269 ; 134.895,35.333 ccw(c140.981,33.703) 139.308,39.777 cw(c173.071,83.412) 118.356,76.329 cw(c173.071,69.245) 139.308,112.88 ; 134.907,117.281 cw(c140.981,118.954) 139.35,112.869

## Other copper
Bottom Layer:
  rectangle net BAT+: 85.242,79.248 87.503,85.344
  rectangle net BAT: 78.715,76.708 82.804,82.753
  rectangle net GND: 78.892,72.593 83.795,75.946

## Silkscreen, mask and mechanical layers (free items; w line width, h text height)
Top Overlay:
  rectangle: 91.491,88.468 105.207,95.961
  lines w0.254: 48.463,28.448 48.971,26.924 ; 48.463,124.46 48.971,125.984 ; 48.717,26.924 49.225,26.924 ; 48.717,125.984 49.225,125.984 ; 48.971,69.192 48.971,26.924 ; 48.971,83.716 48.971,125.984 ; 48.972,125.476 48.971,125.984 ; 49.479,28.448 48.971,26.924 ; 49.479,124.46 48.971,125.984 ; 50.494,126.24 48.971,125.73 ; 50.496,125.224 48.971,125.73 ; 78.304,76.479 78.338,76.445 ; 83.236,76.331 83.307,76.331 ; 90.465,125.794 48.971,125.73 ; 98.353,61.21 98.353,61.28 ; 98.358,91.377 98.358,91.448 ; 106.258,125.818 147.752,125.882 ; 113.632,75.843 113.703,75.843 ; 146.227,126.388 147.752,125.882 ; 146.229,125.372 147.752,125.882 ; 147.752,125.628 147.751,126.136
  text "98.781 (mm)" at 90.72,124.88 h1.52 r0.09
  text "+" at 119.736,102.235 h0.89
  text "+" at 72.009,97.257 h0.89
  text "B+" at 108.61,93.726 h0.89
  text "A2" at 106.045,93.701 h0.89
  text "GND" at 110.795,93.701 h0.89
  text "99.06 (mm)" at 48.057,83.462 h1.52 r270
  text "GND" at 113.055,80.137 h0.89
  text "3.3" at 113.182,77.318 h0.89
  text "JTCK" at 112.293,74.168 h0.89
  text "JTMS" at 112.243,71.933 h0.89
  text "3.3" at 92.329,58.471 h0.89 r90
  text "SCL" at 97.485,58.369 h0.89 r90
  text "GND" at 94.971,58.344 h0.89 r90
  text "SDA" at 100.051,58.293 h0.89 r90
  text "INTA" at 104.953,57.582 h0.89 r90
  text "DRDY" at 106.756,57.582 h0.89 r90
  text "FSYNC" at 102.489,56.617 h0.89 r90
  text "+" at 124.079,54.839 h0.89
  text "+" at 76.835,49.733 h0.89
Bottom Overlay:
  text "Cesare" at 103.353,57.048 h1.78
Top Solder:
  circle w1.27: c55.728,118.948 r5.336
  circle w1.27: c140.97,118.948 r5.336
  circle w1.27: c140.995,33.706 r5.336
  circle w1.27: c55.728,33.731 r5.336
